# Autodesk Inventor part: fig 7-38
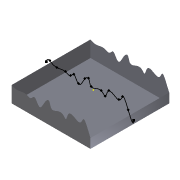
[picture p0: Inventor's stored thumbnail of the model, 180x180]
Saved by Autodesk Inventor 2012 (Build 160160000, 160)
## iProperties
Shininess: 64.0
Length Units: 11269
Angle Units: 11279
Time Units: 11290
Mass Units: 11283
Length Display Precision: 3
Angle Display Precision: 2
Compacted: True
Part Number: fig 7-38
Document SubType Name: Modeling
Created: 2002-12
Designer: deepak
Density: 1 g/cm^3
Material: Default
Density: 0.0
Volumn: 0.0
Area: 0.0
PropertySet Name: Model Information
Control State: 0
Master: False
Checked Out: False
Author: cadcim
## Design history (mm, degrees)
sketch "Sketch1"
  geometry: L1 (-32.188, 30.089)-(27.812, 30.089); L2 (27.812, 30.089)-(27.812, -29.911); L3 (27.812, -29.911)-(-32.188, -29.911); L4 (-32.188, -29.911)-(-32.188, 30.089)
  constraints: 8 end point, 2 parallel, 1 horizontal, 1 perpendicular
  dimensions: "d0" = 60 distance of L1.start L1.end; "d1" = 60 distance of L3.end L1.start
extrude "Extrusion1" new body sketch "Sketch1" stored distance "d2" = 20; taper "d3" = 0 deg
sketch "Sketch2"
  geometry: 17 further points
  constraints: 17 other
extrude_surface "ExtrusionSrf1" sketch "Sketch2" dims "d4" = 70, "d5" = 0
split "Split1"
delete_face "Delete Face1"
node "Sketch5"
sketch "Sketch6"
  geometry: 1 further point
body "Srf1"
body "Srf2"
